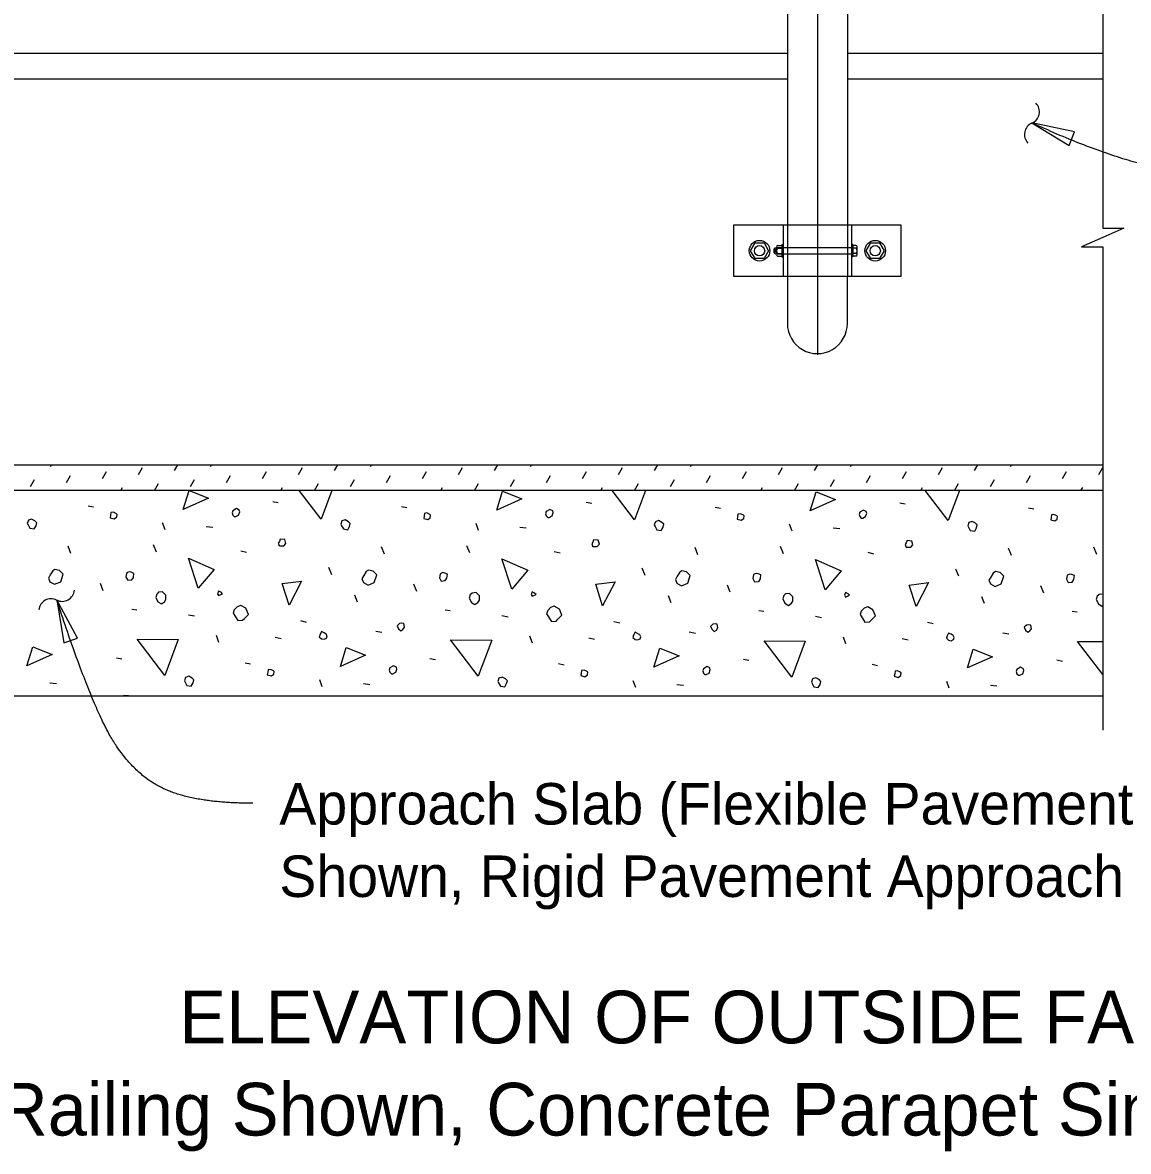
# Model space of a CAD drawing. Extents: x 0 to 72.1, y -15.2 to 30.1.
# Drawn here: x 10.77 to 16.14, y 12.94 to 18.43 of the extents above; entities that cross this region are included whole.
import ezdxf

# ---------------------------------------------------------------- set-up
doc = ezdxf.new("R2010")
doc.units = 0
for name, color, linetype in [('AdhocPoint_dp', 7, 'Continuous'), ('Border', 7, 'Continuous'), ('Patterning', 7, 'Continuous'), ('PlotBorder_dp', 7, 'Continuous'), ('SheetBorder_dp', 7, 'Continuous'), ('TextMisc', 7, 'Continuous')]:
    doc.layers.add(name, color=color, linetype=linetype)

msp = doc.modelspace()

# ---------------------------------------------------------------- linework, layer by layer
at = {"layer": 'AdhocPoint_dp'}
for p, q in [((4.7769, 18.2783), (14.4852, 18.2783)), ((14.7769, 18.2783), (16.018, 18.2783)), ((4.7769, 18.1533), (14.4853, 18.1533)), ((14.7769, 18.1533), (16.018, 18.1533)), ((3.6311, 16.2783), (16.018, 16.2783)), ((16.018, 16.1533), (3.6311, 16.1533)), ((16.018, 15.1533), (3.6311, 15.1533))]:
    msp.add_line(p, q, dxfattribs=at)
at = {"layer": 'Border'}
for p, q in [((14.4852, 17.4432), (14.4852, 17.1932)), ((14.7769, 17.4432), (14.7769, 17.1932)), ((14.7978, 17.3328), (14.4329, 17.3328)), ((14.4329, 17.3029), (14.7978, 17.3029))]:
    msp.add_line(p, q, dxfattribs=at)
at = {"layer": 'Patterning'}
for p, q in [((14.4235, 17.3113), (14.4235, 17.3234)), ((14.4292, 17.3113), (14.4292, 17.3234)), ((10.9037, 16.27), (10.9085, 16.2783)), ((11.1564, 16.2117), (11.1759, 16.2453)), ((11.3315, 16.2311), (11.3509, 16.2647)), ((11.5065, 16.2506), (11.5225, 16.2783)), ((11.6815, 16.27), (11.6863, 16.2783)), ((11.9343, 16.2117), (11.9537, 16.2453)), ((12.1093, 16.2311), (12.1287, 16.2647)), ((12.2843, 16.2506), (12.3003, 16.2783)), ((12.4593, 16.27), (12.4641, 16.2783)), ((12.7121, 16.2117), (12.7315, 16.2453)), ((12.8871, 16.2311), (12.9065, 16.2647)), ((13.0621, 16.2506), (13.0782, 16.2783)), ((13.2371, 16.27), (13.2419, 16.2783)), ((13.4899, 16.2117), (13.5093, 16.2453)), ((13.6649, 16.2311), (13.6844, 16.2647)), ((13.8399, 16.2506), (13.856, 16.2783)), ((14.0149, 16.27), (14.0197, 16.2783)), ((14.2677, 16.2117), (14.2872, 16.2453)), ((14.4427, 16.2311), (14.4622, 16.2647)), ((14.6177, 16.2506), (14.6338, 16.2783)), ((14.7927, 16.27), (14.7975, 16.2783)), ((15.0455, 16.2117), (15.065, 16.2453)), ((15.2205, 16.2311), (15.24, 16.2647)), ((15.3955, 16.2506), (15.4116, 16.2783)), ((15.5706, 16.27), (15.5754, 16.2783)), ((15.8233, 16.2117), (15.8428, 16.2453)), ((15.9984, 16.2311), (16.0178, 16.2647)), ((10.8064, 16.1728), (10.8259, 16.2064)), ((10.9814, 16.1922), (11.0009, 16.2258)), ((11.4092, 16.1533), (11.4287, 16.1869)), ((11.5842, 16.1728), (11.6037, 16.2064)), ((11.7593, 16.1922), (11.7787, 16.2258)), ((12.1871, 16.1533), (12.2065, 16.1869)), ((12.3621, 16.1728), (12.3815, 16.2064)), ((12.5371, 16.1922), (12.5565, 16.2258)), ((12.9649, 16.1533), (12.9843, 16.1869)), ((13.1399, 16.1728), (13.1593, 16.2064)), ((13.3149, 16.1922), (13.3343, 16.2258)), ((13.7427, 16.1533), (13.7621, 16.1869)), ((13.9177, 16.1728), (13.9371, 16.2064)), ((14.0927, 16.1922), (14.1122, 16.2258)), ((14.5205, 16.1533), (14.54, 16.1869)), ((14.6955, 16.1728), (14.715, 16.2064)), ((14.8705, 16.1922), (14.89, 16.2258)), ((15.2983, 16.1533), (15.3178, 16.1869)), ((15.4733, 16.1728), (15.4928, 16.2064)), ((15.6483, 16.1922), (15.6678, 16.2258)), ((11.2455, 16.1533), (11.2537, 16.1675)), ((12.0233, 16.1533), (12.0315, 16.1675)), ((12.8011, 16.1533), (12.8093, 16.1675)), ((13.5789, 16.1533), (13.5871, 16.1675)), ((14.3568, 16.1533), (14.3649, 16.1675)), ((15.1346, 16.1533), (15.1428, 16.1675)), ((15.9124, 16.1533), (15.9206, 16.1675)), ((11.0859, 16.0791), (11.1124, 16.0738)), ((11.984, 16.1003), (12.0105, 16.095)), ((12.6097, 16.0756), (12.6363, 16.0703)), ((13.5078, 16.0968), (13.5343, 16.0915)), ((15.0316, 16.0932), (15.0581, 16.0879)), ((14.1336, 16.072), (14.1601, 16.0667)), ((15.6574, 16.0685), (15.6839, 16.0632)), ((11.4607, 15.9624), (11.4483, 15.996)), ((11.6604, 15.9783), (11.6923, 15.9748)), ((12.9845, 15.9589), (12.9721, 15.9925)), ((13.1843, 15.9748), (13.2161, 15.9713)), ((14.5083, 15.9553), (14.4959, 15.9889)), ((14.7081, 15.9713), (14.7399, 15.9677)), ((11.0028, 15.8475), (10.9887, 15.8829)), ((11.4183, 15.8528), (11.4041, 15.8882)), ((11.8284, 15.8599), (11.8567, 15.8528)), ((12.5267, 15.844), (12.5125, 15.8793)), ((12.9421, 15.8493), (12.9279, 15.8846)), ((13.3522, 15.8564), (13.3805, 15.8493)), ((14.0505, 15.8404), (14.0363, 15.8758)), ((14.4659, 15.8457), (14.4518, 15.8811)), ((15.5743, 15.8369), (15.5601, 15.8723)), ((15.9897, 15.8422), (15.9756, 15.8776)), ((14.876, 15.8528), (14.9043, 15.8457)), ((12.2703, 15.7432), (12.2562, 15.7786)), ((13.7941, 15.7397), (13.78, 15.775)), ((15.318, 15.7361), (15.3038, 15.7715)), ((11.1602, 15.6654), (11.146, 15.7008)), ((12.684, 15.6619), (12.6698, 15.6973)), ((14.2078, 15.6584), (14.1937, 15.6937)), ((15.7316, 15.6548), (15.7175, 15.6902)), ((12.3958, 15.6106), (12.3835, 15.6442)), ((13.9197, 15.6071), (13.9073, 15.6407)), ((15.4435, 15.6036), (15.4311, 15.6371)), ((11.2981, 15.577), (11.3228, 15.5735)), ((11.5738, 15.5488), (11.6039, 15.5435)), ((12.8219, 15.5735), (12.8466, 15.57)), ((13.0976, 15.5452), (13.1277, 15.5399)), ((14.3457, 15.57), (14.3704, 15.5664)), ((14.6215, 15.5417), (14.6515, 15.5364)), ((15.8695, 15.5664), (15.8943, 15.5629)), ((12.1183, 15.5205), (12.1466, 15.5134)), ((12.4842, 15.4692), (12.5143, 15.4639)), ((13.6421, 15.5169), (13.6704, 15.5099)), ((15.1659, 15.5134), (15.1942, 15.5063)), ((11.7223, 15.4144), (11.7099, 15.448)), ((11.9963, 15.4409), (12.0246, 15.4339)), ((13.2461, 15.4109), (13.2338, 15.4445)), ((13.5201, 15.4374), (13.5484, 15.4303)), ((14.008, 15.4657), (14.0381, 15.4604)), ((14.77, 15.4073), (14.7576, 15.4409)), ((15.044, 15.4339), (15.0722, 15.4268)), ((15.5319, 15.4621), (15.5619, 15.4568)), ((11.2238, 15.3402), (11.2503, 15.3349)), ((11.8496, 15.3154), (11.8761, 15.3101)), ((12.7476, 15.3366), (12.7741, 15.3313)), ((13.3734, 15.3119), (13.3999, 15.3066)), ((14.2714, 15.3331), (14.298, 15.3278)), ((14.8972, 15.3083), (14.9237, 15.303)), ((15.7953, 15.3296), (15.8218, 15.3243)), ((10.9003, 15.2182), (10.9321, 15.2147)), ((12.2244, 15.1987), (12.212, 15.2323)), ((12.4241, 15.2147), (12.4559, 15.2111)), ((13.7482, 15.1952), (13.7358, 15.2288)), ((13.9479, 15.2111), (13.9798, 15.2076)), ((15.272, 15.1917), (15.2596, 15.2253)), ((15.4718, 15.2076), (15.5036, 15.204))]:
    msp.add_line(p, q, dxfattribs=at)
for points in [[(11.5491, 16.0614), (11.5774, 16.1533), (11.6711, 16.1162), (11.5491, 16.0614)], [(12.2191, 16.0137), (12.1129, 16.1533)], [(12.2713, 16.1533), (12.2191, 16.0137)], [(13.0729, 16.0579), (13.1012, 16.1498), (13.1949, 16.1127), (13.0729, 16.0579)], [(13.7429, 16.0101), (13.6341, 16.1533)], [(13.7964, 16.1533), (13.7429, 16.0101)], [(14.5967, 16.0543), (14.625, 16.1463), (14.7187, 16.1091), (14.5967, 16.0543)], [(15.2667, 16.0066), (15.1552, 16.1533)], [(15.3215, 16.1533), (15.2667, 16.0066)], [(11.1938, 16.0208), (11.2132, 16.0155), (11.2256, 16.0243), (11.2273, 16.0367), (11.2238, 16.0402), (11.2097, 16.0473), (11.1973, 16.0455), (11.1955, 16.0331), (11.1938, 16.0208)], [(11.7966, 16.0261), (11.8036, 16.0261), (11.8178, 16.0331), (11.8231, 16.049), (11.8213, 16.0579), (11.8072, 16.0649), (11.7895, 16.0543), (11.786, 16.0437), (11.7895, 16.0331), (11.7966, 16.0261)], [(12.7176, 16.0172), (12.737, 16.0119), (12.7494, 16.0208), (12.7512, 16.0331), (12.7476, 16.0367), (12.7335, 16.0437), (12.7211, 16.042), (12.7193, 16.0296), (12.7176, 16.0172)], [(13.3204, 16.0225), (13.3275, 16.0225), (13.3416, 16.0296), (13.3469, 16.0455), (13.3451, 16.0543), (13.331, 16.0614), (13.3133, 16.0508), (13.3098, 16.0402), (13.3133, 16.0296), (13.3204, 16.0225)], [(14.2414, 16.0137), (14.2608, 16.0084), (14.2732, 16.0172), (14.275, 16.0296), (14.2714, 16.0331), (14.2573, 16.0402), (14.2449, 16.0384), (14.2432, 16.0261), (14.2414, 16.0137)], [(14.8442, 16.019), (14.8513, 16.019), (14.8654, 16.0261), (14.8707, 16.042), (14.8689, 16.0508), (14.8548, 16.0579), (14.8371, 16.0473), (14.8336, 16.0367), (14.8371, 16.0261), (14.8442, 16.019)], [(15.7652, 16.0101), (15.7847, 16.0048), (15.797, 16.0137), (15.7988, 16.0261), (15.7953, 16.0296), (15.7811, 16.0367), (15.7687, 16.0349), (15.767, 16.0225), (15.7652, 16.0101)], [(10.7942, 15.9854), (10.8031, 15.9695), (10.8243, 15.966), (10.8331, 15.9819), (10.8367, 15.996), (10.8278, 16.0048), (10.8119, 16.0137), (10.796, 16.0084), (10.7907, 15.9925), (10.7942, 15.9854)], [(12.3181, 15.9819), (12.3269, 15.966), (12.3481, 15.9624), (12.3569, 15.9783), (12.3605, 15.9925), (12.3516, 16.0013), (12.3357, 16.0101), (12.3198, 16.0048), (12.3145, 15.9889), (12.3181, 15.9819)], [(13.8419, 15.9783), (13.8507, 15.9624), (13.8719, 15.9589), (13.8808, 15.9748), (13.8843, 15.9889), (13.8755, 15.9978), (13.8596, 16.0066), (13.8436, 16.0013), (13.8383, 15.9854), (13.8419, 15.9783)], [(15.3657, 15.9748), (15.3745, 15.9589), (15.3957, 15.9553), (15.4046, 15.9713), (15.4081, 15.9854), (15.3993, 15.9942), (15.3834, 16.0031), (15.3675, 15.9978), (15.3622, 15.9819), (15.3657, 15.9748)], [(12.0158, 15.8846), (12.037, 15.8846), (12.0476, 15.8952), (12.0423, 15.9147), (12.0193, 15.9165), (12.0158, 15.9058), (12.0105, 15.897), (12.0158, 15.8846), (12.0122, 15.8882)], [(13.5396, 15.8811), (13.5608, 15.8811), (13.5714, 15.8917), (13.5661, 15.9112), (13.5431, 15.9129), (13.5396, 15.9023), (13.5343, 15.8935), (13.5396, 15.8811), (13.5361, 15.8846)], [(15.0634, 15.8776), (15.0846, 15.8776), (15.0952, 15.8882), (15.0899, 15.9076), (15.0669, 15.9094), (15.0634, 15.8988), (15.0581, 15.8899), (15.0634, 15.8776), (15.0599, 15.8811)], [(11.6216, 15.6778), (11.5738, 15.8245), (11.6993, 15.7697), (11.6216, 15.6778)], [(13.1454, 15.6743), (13.0976, 15.821), (13.2232, 15.7662), (13.1454, 15.6743)], [(14.6692, 15.6707), (14.6215, 15.8175), (14.747, 15.7627), (14.6692, 15.6707)], [(10.9003, 15.7096), (10.9233, 15.6973), (10.9533, 15.7096), (10.9657, 15.7468), (10.948, 15.7644), (10.9251, 15.7697), (10.9145, 15.7627), (10.9021, 15.7432), (10.8932, 15.7273), (10.9003, 15.7096)], [(11.2698, 15.7326), (11.2786, 15.7167), (11.2981, 15.7185), (11.3069, 15.7308), (11.3087, 15.7503), (11.2963, 15.7556), (11.2875, 15.7574), (11.2768, 15.7538), (11.2733, 15.7503), (11.2698, 15.7326)], [(12.4241, 15.7061), (12.4471, 15.6937), (12.4772, 15.7061), (12.4895, 15.7432), (12.4719, 15.7609), (12.4489, 15.7662), (12.4383, 15.7591), (12.4259, 15.7397), (12.4171, 15.7238), (12.4241, 15.7061)], [(12.7936, 15.7291), (12.8024, 15.7132), (12.8219, 15.7149), (12.8307, 15.7273), (12.8325, 15.7468), (12.8201, 15.7521), (12.8113, 15.7538), (12.8007, 15.7503), (12.7971, 15.7468), (12.7936, 15.7291)], [(13.9479, 15.7026), (13.9709, 15.6902), (14.001, 15.7026), (14.0133, 15.7397), (13.9957, 15.7574), (13.9727, 15.7627), (13.9621, 15.7556), (13.9497, 15.7361), (13.9409, 15.7202), (13.9479, 15.7026)], [(14.3174, 15.7255), (14.3262, 15.7096), (14.3457, 15.7114), (14.3545, 15.7238), (14.3563, 15.7432), (14.3439, 15.7485), (14.3351, 15.7503), (14.3245, 15.7468), (14.3209, 15.7432), (14.3174, 15.7255)], [(15.4718, 15.699), (15.4947, 15.6866), (15.5248, 15.699), (15.5372, 15.7361), (15.5195, 15.7538), (15.4965, 15.7591), (15.4859, 15.7521), (15.4735, 15.7326), (15.4647, 15.7167), (15.4718, 15.699)], [(15.8412, 15.722), (15.8501, 15.7061), (15.8695, 15.7079), (15.8783, 15.7202), (15.8801, 15.7397), (15.8677, 15.745), (15.8589, 15.7468), (15.8483, 15.7432), (15.8448, 15.7397), (15.8412, 15.722)], [(12.0635, 15.5965), (12.0299, 15.7008), (12.1236, 15.7132), (12.0635, 15.5965)], [(13.5873, 15.593), (13.5537, 15.6973), (13.6474, 15.7096), (13.5873, 15.593)], [(15.1111, 15.5894), (15.0775, 15.6937), (15.1712, 15.7061), (15.1111, 15.5894)], [(11.4147, 15.6336), (11.4253, 15.6124), (11.443, 15.6018), (11.4572, 15.6124), (11.4642, 15.623), (11.4642, 15.6442), (11.4483, 15.6601), (11.4289, 15.6584), (11.42, 15.6495), (11.4147, 15.6336)], [(11.7206, 15.6425), (11.74, 15.6513), (11.7329, 15.6584), (11.7206, 15.6637), (11.7153, 15.6513), (11.7206, 15.6425)], [(12.9385, 15.6301), (12.9492, 15.6089), (12.9668, 15.5983), (12.981, 15.6089), (12.988, 15.6195), (12.988, 15.6407), (12.9721, 15.6566), (12.9527, 15.6548), (12.9438, 15.646), (12.9385, 15.6301)], [(13.2444, 15.6389), (13.2638, 15.6478), (13.2567, 15.6548), (13.2444, 15.6601), (13.2391, 15.6478), (13.2444, 15.6389)], [(14.4624, 15.6265), (14.473, 15.6053), (14.4906, 15.5947), (14.5048, 15.6053), (14.5119, 15.6159), (14.5119, 15.6371), (14.4959, 15.6531), (14.4765, 15.6513), (14.4677, 15.6425), (14.4624, 15.6265)], [(14.7682, 15.6354), (14.7876, 15.6442), (14.7806, 15.6513), (14.7682, 15.6566), (14.7629, 15.6442), (14.7682, 15.6354)], [(16.018, 15.6494), (16.0003, 15.6478), (15.9915, 15.6389), (15.9862, 15.623)], [(11.7913, 15.5576), (11.8142, 15.5205), (11.8372, 15.5222), (11.8461, 15.5311), (11.8655, 15.5505), (11.8531, 15.5806), (11.8284, 15.5947), (11.8107, 15.5877), (11.7966, 15.5735), (11.7913, 15.5576)], [(13.3151, 15.5541), (13.3381, 15.5169), (13.361, 15.5187), (13.3699, 15.5275), (13.3893, 15.547), (13.377, 15.577), (13.3522, 15.5912), (13.3345, 15.5841), (13.3204, 15.57), (13.3151, 15.5541)], [(14.8389, 15.5505), (14.8619, 15.5134), (14.8849, 15.5152), (14.8937, 15.524), (14.9131, 15.5435), (14.9008, 15.5735), (14.876, 15.5877), (14.8583, 15.5806), (14.8442, 15.5664), (14.8389, 15.5505)], [(15.9862, 15.623), (15.9968, 15.6018), (16.0145, 15.5912), (16.018, 15.5938)], [(12.5956, 15.4816), (12.6062, 15.471), (12.6168, 15.478), (12.6239, 15.4887), (12.6203, 15.5063), (12.6115, 15.5081), (12.5991, 15.5063), (12.5885, 15.4957), (12.5956, 15.4816)], [(14.1194, 15.478), (14.13, 15.4674), (14.1406, 15.4745), (14.1477, 15.4851), (14.1442, 15.5028), (14.1353, 15.5046), (14.1229, 15.5028), (14.1123, 15.4922), (14.1194, 15.478)], [(15.6432, 15.4745), (15.6538, 15.4639), (15.6644, 15.471), (15.6715, 15.4816), (15.668, 15.4993), (15.6591, 15.501), (15.6468, 15.4993), (15.6362, 15.4887), (15.6432, 15.4745)], [(11.4589, 15.2535), (11.3246, 15.4303), (11.5243, 15.4286), (11.4589, 15.2535)], [(12.2208, 15.4321), (12.2332, 15.4303), (12.2456, 15.4356), (12.2491, 15.4462), (12.2438, 15.4551), (12.2332, 15.4621), (12.2208, 15.4674), (12.2138, 15.4533), (12.2102, 15.4427), (12.2208, 15.4321)], [(12.9827, 15.25), (12.8484, 15.4268), (13.0481, 15.425), (12.9827, 15.25)], [(13.7446, 15.4286), (13.757, 15.4268), (13.7694, 15.4321), (13.7729, 15.4427), (13.7676, 15.4515), (13.757, 15.4586), (13.7446, 15.4639), (13.7376, 15.4498), (13.734, 15.4392), (13.7446, 15.4286)], [(14.5066, 15.2465), (14.3722, 15.4232), (14.572, 15.4215), (14.5066, 15.2465)], [(15.2685, 15.425), (15.2808, 15.4232), (15.2932, 15.4286), (15.2967, 15.4392), (15.2914, 15.448), (15.2808, 15.4551), (15.2685, 15.4604), (15.2614, 15.4462), (15.2579, 15.4356), (15.2685, 15.425)], [(16.018, 15.2592), (15.896, 15.4197), (16.018, 15.4186)], [(10.7889, 15.3013), (10.8172, 15.3932), (10.9109, 15.3561), (10.7889, 15.3013)], [(12.3128, 15.2977), (12.341, 15.3897), (12.4347, 15.3525), (12.3128, 15.2977)], [(13.8366, 15.2942), (13.8649, 15.3861), (13.9585, 15.349), (13.8366, 15.2942)], [(15.3604, 15.2907), (15.3887, 15.3826), (15.4824, 15.3455), (15.3604, 15.2907)], [(11.5579, 15.2217), (11.5668, 15.2058), (11.588, 15.2023), (11.5968, 15.2182), (11.6003, 15.2323), (11.5915, 15.2412), (11.5756, 15.25), (11.5597, 15.2447), (11.5544, 15.2288), (11.5579, 15.2217)], [(11.9574, 15.2571), (11.9769, 15.2518), (11.9893, 15.2606), (11.991, 15.273), (11.9875, 15.2765), (11.9733, 15.2836), (11.961, 15.2818), (11.9592, 15.2695), (11.9574, 15.2571)], [(12.5602, 15.2624), (12.5673, 15.2624), (12.5815, 15.2695), (12.5868, 15.2854), (12.585, 15.2942), (12.5708, 15.3013), (12.5532, 15.2907), (12.5496, 15.2801), (12.5532, 15.2695), (12.5602, 15.2624)], [(13.4812, 15.2535), (13.5007, 15.2482), (13.5131, 15.2571), (13.5148, 15.2695), (13.5113, 15.273), (13.4972, 15.2801), (13.4848, 15.2783), (13.483, 15.2659), (13.4812, 15.2535)], [(14.0841, 15.2588), (14.0911, 15.2588), (14.1053, 15.2659), (14.1106, 15.2818), (14.1088, 15.2907), (14.0947, 15.2977), (14.077, 15.2871), (14.0735, 15.2765), (14.077, 15.2659), (14.0841, 15.2588)], [(15.0051, 15.25), (15.0245, 15.2447), (15.0369, 15.2535), (15.0387, 15.2659), (15.0351, 15.2695), (15.021, 15.2765), (15.0086, 15.2748), (15.0068, 15.2624), (15.0051, 15.25)], [(15.6079, 15.2553), (15.6149, 15.2553), (15.6291, 15.2624), (15.6344, 15.2783), (15.6326, 15.2871), (15.6185, 15.2942), (15.6008, 15.2836), (15.5973, 15.273), (15.6008, 15.2624), (15.6079, 15.2553)], [(13.0817, 15.2182), (13.0906, 15.2023), (13.1118, 15.1987), (13.1206, 15.2147), (13.1242, 15.2288), (13.1153, 15.2376), (13.0994, 15.2465), (13.0835, 15.2412), (13.0782, 15.2253), (13.0817, 15.2182)], [(14.6055, 15.2147), (14.6144, 15.1987), (14.6356, 15.1952), (14.6444, 15.2111), (14.648, 15.2253), (14.6391, 15.2341), (14.6232, 15.2429), (14.6073, 15.2376), (14.602, 15.2217), (14.6055, 15.2147)], [(11.2825, 15.1533), (11.2821, 15.1545), (11.2592, 15.1563), (11.2582, 15.1533)]]:
    msp.add_lwpolyline(points, dxfattribs=at)
at = {"layer": 'PlotBorder_dp'}
msp.add_lwpolyline([(16.018, 19.2784), (16.018, 17.4276), (16.1214, 17.4276), (16.018, 17.3826), (15.9147, 17.3376), (16.018, 17.3376), (16.018, 14.9877)], dxfattribs=at)
for points in [[(15.6743, 17.939), (15.8552, 17.83), (15.881, 17.8956)], [(10.9339, 15.621), (10.9685, 15.4127), (11.0352, 15.4357)]]:
    msp.add_lwpolyline(points, close=True, dxfattribs=at)
for centre, start, end in [((15.6511, 17.9932), 292.7091, 44.4364), ((15.6971, 17.8833), 112.7091, 224.4364), ((10.9601, 15.6739), 243.2317, 354.9589), ((10.9064, 15.5675), 63.2317, 174.9589)]:
    msp.add_arc(centre, 0.0596, start, end, dxfattribs=at)
for points in [[(17.0013, 17.682), (16.9314, 17.682), (16.232, 17.682), (15.6743, 17.939)], [(11.8875, 14.6332), (11.6222, 14.6332), (11.3236, 14.7577), (11.108, 15.0898), (10.9339, 15.621)]]:
    msp.add_open_spline(points, degree=2, dxfattribs=at)
at = {"layer": 'SheetBorder_dp'}
msp.add_line((14.631, 27.059), (14.631, 16.8122), dxfattribs=at)
at = {"layer": 'TextMisc'}
for p, q in [((14.4852, 18.6932), (14.4852, 17.4432)), ((14.7769, 18.6932), (14.7769, 17.4432)), ((14.2251, 17.4432), (15.0371, 17.4432)), ((14.2251, 17.1932), (14.2251, 17.4432)), ((14.4644, 17.4432), (14.4644, 17.1932)), ((14.7977, 17.4432), (14.7977, 17.1932)), ((15.0371, 17.4432), (15.0371, 17.1932)), ((14.4329, 17.3361), (14.4329, 17.3004)), ((14.4378, 17.3442), (14.4579, 17.3442)), ((14.4579, 17.3485), (14.4579, 17.2879)), ((14.4579, 17.3485), (14.4644, 17.3485)), ((14.4579, 17.3442), (14.4579, 17.2922)), ((14.804, 17.3485), (14.798, 17.3485)), ((14.804, 17.3485), (14.804, 17.2879)), ((14.8187, 17.3442), (14.804, 17.3442)), ((14.8238, 17.2988), (14.8238, 17.3377)), ((14.4207, 17.3262), (14.4263, 17.3328)), ((14.4207, 17.3085), (14.4207, 17.3262)), ((14.4207, 17.3085), (14.4263, 17.3029)), ((14.4263, 17.3328), (14.4329, 17.3328)), ((14.4263, 17.3029), (14.4263, 17.3328)), ((14.4263, 17.3029), (14.4329, 17.3029)), ((14.4376, 17.3312), (14.4579, 17.3312)), ((14.4376, 17.3053), (14.4579, 17.3053)), ((14.4379, 17.2922), (14.4579, 17.2922)), ((14.4579, 17.2879), (14.4644, 17.2879)), ((14.804, 17.2879), (14.798, 17.2879)), ((14.8189, 17.3312), (14.804, 17.3312)), ((14.8189, 17.3052), (14.804, 17.3052)), ((14.8187, 17.2922), (14.804, 17.2922)), ((15.0371, 17.1932), (14.2251, 17.1932)), ((14.4851, 17.1932), (14.4851, 16.964)), ((14.7768, 16.964), (14.7768, 17.1932))]:
    msp.add_line(p, q, dxfattribs=at)
for points in [[(14.3284, 17.3557), (14.3718, 17.3557), (14.3934, 17.3182), (14.3718, 17.2807), (14.3284, 17.2807), (14.3067, 17.3182)], [(14.8904, 17.3557), (14.9337, 17.3557), (14.9554, 17.3182), (14.9337, 17.2807), (14.8904, 17.2807), (14.8687, 17.3182)]]:
    msp.add_lwpolyline(points, close=True, dxfattribs=at)
for centre, radius in [((14.3501, 17.3182), 0.05), ((14.3501, 17.3182), 0.025), ((14.9121, 17.3182), 0.05), ((14.9121, 17.3182), 0.025)]:
    msp.add_circle(centre, radius, dxfattribs=at)
for centre, radius, start, end in [((14.4394, 17.3377), 0.00674, 104.4891, 254.1889), ((14.817, 17.3376), 0.00673, 285.7823, 75.5404), ((14.4523, 17.3182), 0.0196, 138.628, 221.372), ((14.4394, 17.2987), 0.00673, 105.7823, 255.5404), ((14.817, 17.2987), 0.00674, 284.4891, 74.1889), ((14.8041, 17.3182), 0.0196, 318.628, 41.372)]:
    msp.add_arc(centre, radius, start, end, dxfattribs=at)
msp.add_ellipse((14.631, 16.964), major_axis=(0, 0.1458), ratio=0.999499, start_param=1.570796, end_param=4.712389, dxfattribs=at)

# ---------------------------------------------------------------- texts
at = {"layer": 'PlotBorder_dp'}
for s, height, p in [('Approach Slab (Flexible Pavement Approach Slab ', 0.2016, (12.0159, 14.5298)), ('Shown, Rigid Pavement Approach Slab Similar)', 0.2016, (12.0159, 14.1778)), ('ELEVATION OF OUTSIDE FACE OF RAILING', 0.256001, (11.5294, 13.4666)), ('(Traffic Railing Shown, Concrete Parapet Similar) (See Note 3)', 0.256001, (9.4828, 13.0186))]:
    msp.add_text(s, height=height, dxfattribs=at).set_placement(p)

doc.saveas('drawing.dxf')
